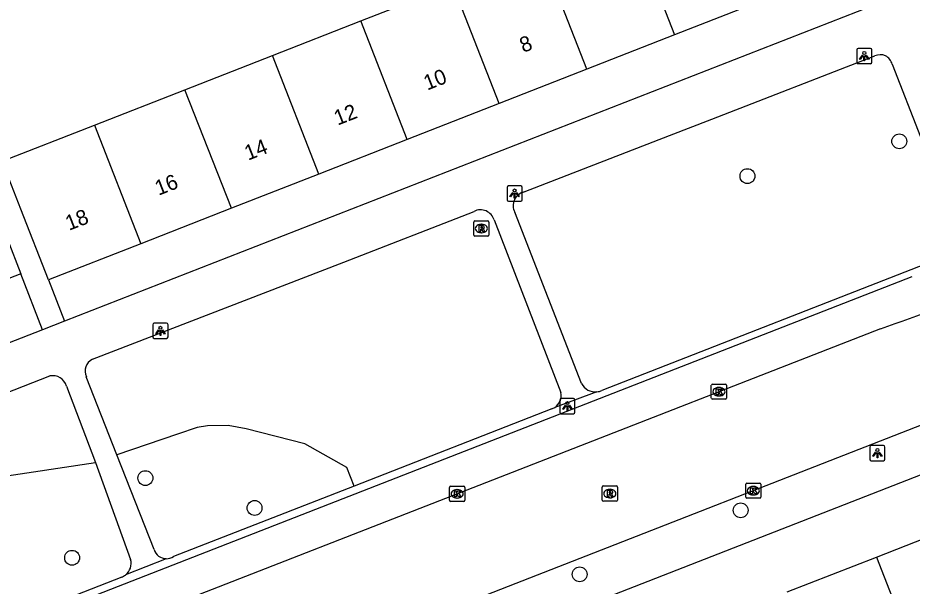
# Model space of a CAD drawing. Extents: x 159689 to 160786, y 387323 to 388339.
# Drawn here: x 160126.1 to 160185.1, y 387702.9 to 387740.3 of the extents above; entities that cross this region are included whole.
import ezdxf

# ---------------------------------------------------------------- set-up
doc = ezdxf.new("R2010")
doc.units = 0
for name, color, linetype in [('IMGEO_Boom', 7, 'Continuous'), ('IMGEO_Groenvoorziening', 7, 'Continuous'), ('IMGEO_Kolk', 7, 'Continuous'), ('IMGEO_Lichtpunt', 7, 'Continuous'), ('IMGEO_Pand', 7, 'Continuous'), ('IMGEO_Pand_nummerreeks', 7, 'Continuous'), ('IMGEO_Rijbaan_lokaal_open', 7, 'Continuous'), ('IMGEO_Rioolput', 7, 'Continuous'), ('IMGEO_Voetpad_open', 7, 'Continuous')]:
    doc.layers.add(name, color=color, linetype=linetype)

msp = doc.modelspace()

# ---------------------------------------------------------------- linework, layer by layer
at = {"layer": 'IMGEO_Boom'}
for centre in [(160184.219, 387732.211), (160174.216, 387729.919), (160134.54, 387710.022), (160141.733, 387708.056), (160173.765, 387707.9), (160129.711, 387704.77), (160163.156, 387703.68)]:
    msp.add_circle(centre, 0.489, dxfattribs=at)
at = {"layer": 'IMGEO_Groenvoorziening'}
for points in [[(160148.302, 387709.499), (160147.822, 387710.72), (160145.048, 387712.284), (160141.184, 387713.26), (160139.991, 387713.483), (160138.623, 387713.466), (160137.948, 387713.351), (160136.653, 387712.912), (160132.659, 387711.561)], [(160102.286, 387697.335), (160106.239, 387698.209), (160113.688, 387699.856), (160119.673, 387708.148), (160120.152, 387708.72), (160120.74, 387709.179), (160121.41, 387709.507), (160122.18, 387709.694), (160131.248, 387711.047)]]:
    msp.add_lwpolyline(points, dxfattribs=at)
at = {"layer": 'IMGEO_Kolk'}
for p, q in [((160171.834, 387715.286), (160171.834, 387716.138)), ((160171.909, 387716.212), (160172.761, 387716.212)), ((160172.835, 387716.138), (160172.835, 387715.286)), ((160172.322, 387715.992), (160172.347, 387715.992)), ((160172.761, 387715.212), (160171.909, 387715.212)), ((160172.345, 387715.432), (160172.32, 387715.432)), ((160174.103, 387708.763), (160174.103, 387709.615)), ((160174.178, 387709.689), (160175.03, 387709.689)), ((160175.104, 387709.615), (160175.104, 387708.763)), ((160154.584, 387708.559), (160154.584, 387709.411)), ((160154.659, 387709.485), (160155.511, 387709.485)), ((160155.072, 387709.265), (160155.097, 387709.265)), ((160155.585, 387709.411), (160155.585, 387708.559)), ((160174.591, 387709.469), (160174.616, 387709.469)), ((160155.511, 387708.485), (160154.659, 387708.485)), ((160155.095, 387708.705), (160155.07, 387708.705)), ((160175.03, 387708.689), (160174.178, 387708.689)), ((160174.614, 387708.909), (160174.589, 387708.909))]:
    msp.add_line(p, q, dxfattribs=at)
for points in [[(160171.834, 387715.286), (160171.834, 387716.138)], [(160171.909, 387716.212), (160172.761, 387716.212)], [(160172.835, 387716.138), (160172.835, 387715.286)], [(160172.155, 387715.912), (160172.278, 387715.912), (160172.278, 387715.761), (160172.408, 387715.912), (160172.572, 387715.912), (160172.426, 387715.761), (160172.579, 387715.512), (160172.427, 387715.512), (160172.342, 387715.676), (160172.278, 387715.609), (160172.278, 387715.512), (160172.155, 387715.512), (160172.155, 387715.912)], [(160172.761, 387715.212), (160171.909, 387715.212)], [(160174.103, 387708.763), (160174.103, 387709.615)], [(160174.178, 387709.689), (160175.03, 387709.689)], [(160175.104, 387709.615), (160175.104, 387708.763)], [(160154.584, 387708.559), (160154.584, 387709.411)], [(160154.659, 387709.485), (160155.511, 387709.485)], [(160154.905, 387709.185), (160155.028, 387709.185), (160155.028, 387709.034), (160155.158, 387709.185), (160155.322, 387709.185), (160155.176, 387709.034), (160155.329, 387708.785), (160155.177, 387708.785), (160155.092, 387708.949), (160155.028, 387708.882), (160155.028, 387708.785), (160154.905, 387708.785), (160154.905, 387709.185)], [(160155.585, 387709.411), (160155.585, 387708.559)], [(160174.424, 387709.389), (160174.547, 387709.389), (160174.547, 387709.238), (160174.677, 387709.389), (160174.841, 387709.389), (160174.695, 387709.238), (160174.848, 387708.989), (160174.696, 387708.989), (160174.611, 387709.153), (160174.547, 387709.086), (160174.547, 387708.989), (160174.424, 387708.989), (160174.424, 387709.389)], [(160155.511, 387708.485), (160154.659, 387708.485)], [(160175.03, 387708.689), (160174.178, 387708.689)]]:
    msp.add_lwpolyline(points, dxfattribs=at)
for centre, start, end in [((160171.911, 387716.136), 91.55205, 178.44795), ((160171.911, 387716.136), 91.55205, 178.44795), ((160172.759, 387716.136), 1.55205, 88.44795), ((160172.759, 387716.136), 1.55205, 88.44795), ((160171.911, 387715.288), 181.55205, 268.44795), ((160171.911, 387715.288), 181.55205, 268.44795), ((160172.759, 387715.288), 271.55205, 358.44795), ((160172.759, 387715.288), 271.55205, 358.44795), ((160174.18, 387709.613), 91.55205, 178.44795), ((160174.18, 387709.613), 91.55205, 178.44795), ((160175.028, 387709.613), 1.55205, 88.44795), ((160175.028, 387709.613), 1.55205, 88.44795), ((160154.661, 387709.409), 91.55205, 178.44795), ((160154.661, 387709.409), 91.55205, 178.44795), ((160155.509, 387709.409), 1.55205, 88.44795), ((160155.509, 387709.409), 1.55205, 88.44795), ((160154.661, 387708.561), 181.55205, 268.44795), ((160154.661, 387708.561), 181.55205, 268.44795), ((160155.509, 387708.561), 271.55205, 358.44795), ((160155.509, 387708.561), 271.55205, 358.44795), ((160174.18, 387708.765), 181.55205, 268.44795), ((160174.18, 387708.765), 181.55205, 268.44795), ((160175.028, 387708.765), 271.55205, 358.44795), ((160175.028, 387708.765), 271.55205, 358.44795)]:
    msp.add_arc(centre, 0.0765, start, end, dxfattribs=at)
for centre, major_axis, ratio, start_param, end_param in [((160172.321, 387715.712), (-0.387, 0.002), 0.722429, 4.712389, 7.853982), ((160172.346, 387715.712), (-0.39, 0.002), 0.717154, 1.570796, 4.712389), ((160155.071, 387708.985), (-0.387, 0.002), 0.722429, 4.712389, 7.853982), ((160155.096, 387708.985), (-0.39, 0.002), 0.717154, 1.570796, 4.712389), ((160174.59, 387709.189), (-0.387, 0.002), 0.722429, 4.712389, 7.853982), ((160174.615, 387709.189), (-0.39, 0.002), 0.717154, 1.570796, 4.712389)]:
    msp.add_ellipse(centre, major_axis=major_axis, ratio=ratio, start_param=start_param, end_param=end_param, dxfattribs=at)
at = {"layer": 'IMGEO_Lichtpunt'}
for p, q in [((160181.415, 387738.231), (160181.415, 387737.424)), ((160181.415, 387738.231), (160181.415, 387737.424)), ((160182.317, 387738.326), (160181.509, 387738.326)), ((160182.317, 387738.326), (160181.509, 387738.326)), ((160182.411, 387737.424), (160182.411, 387738.231)), ((160182.411, 387737.424), (160182.411, 387738.231)), ((160181.509, 387737.33), (160182.317, 387737.33)), ((160181.509, 387737.33), (160182.317, 387737.33)), ((160158.37, 387729.175), (160158.37, 387728.368)), ((160158.37, 387729.175), (160158.37, 387728.368)), ((160159.272, 387729.27), (160158.464, 387729.27)), ((160159.272, 387729.27), (160158.464, 387729.27)), ((160159.366, 387728.368), (160159.366, 387729.175)), ((160159.366, 387728.368), (160159.366, 387729.175)), ((160158.464, 387728.274), (160159.272, 387728.274)), ((160158.464, 387728.274), (160159.272, 387728.274)), ((160135.935, 387720.226), (160135.127, 387720.226)), ((160135.935, 387720.226), (160135.127, 387720.226)), ((160135.033, 387720.131), (160135.033, 387719.324)), ((160135.033, 387720.131), (160135.033, 387719.324)), ((160136.029, 387719.324), (160136.029, 387720.131)), ((160136.029, 387719.324), (160136.029, 387720.131)), ((160135.127, 387719.23), (160135.935, 387719.23)), ((160135.127, 387719.23), (160135.935, 387719.23)), ((160161.853, 387715.167), (160161.853, 387714.36)), ((160161.853, 387715.167), (160161.853, 387714.36)), ((160162.755, 387715.262), (160161.947, 387715.262)), ((160162.755, 387715.262), (160161.947, 387715.262)), ((160162.849, 387714.36), (160162.849, 387715.167)), ((160162.849, 387714.36), (160162.849, 387715.167)), ((160161.947, 387714.266), (160162.755, 387714.266)), ((160161.947, 387714.266), (160162.755, 387714.266)), ((160182.28, 387712.071), (160182.28, 387711.264)), ((160182.28, 387712.071), (160182.28, 387711.264)), ((160183.182, 387712.166), (160182.374, 387712.166)), ((160183.182, 387712.166), (160182.374, 387712.166)), ((160183.276, 387711.264), (160183.276, 387712.071)), ((160183.276, 387711.264), (160183.276, 387712.071)), ((160182.374, 387711.17), (160183.182, 387711.17)), ((160182.374, 387711.17), (160183.182, 387711.17))]:
    msp.add_line(p, q, dxfattribs=at)
for points in [[(160181.789, 387737.895), (160181.828, 387737.867), (160181.64, 387737.605), (160181.602, 387737.632), (160181.789, 387737.895)], [(160182.001, 387737.867), (160182.039, 387737.894), (160182.226, 387737.632), (160182.187, 387737.604), (160182.001, 387737.867)], [(160181.891, 387737.847), (160181.938, 387737.847), (160181.938, 387737.525), (160181.891, 387737.525), (160181.891, 387737.847)], [(160158.744, 387728.839), (160158.783, 387728.811), (160158.595, 387728.549), (160158.557, 387728.576), (160158.744, 387728.839)], [(160158.846, 387728.791), (160158.893, 387728.791), (160158.893, 387728.469), (160158.846, 387728.469), (160158.846, 387728.791)], [(160158.956, 387728.811), (160158.994, 387728.838), (160159.181, 387728.576), (160159.142, 387728.548), (160158.956, 387728.811)], [(160135.407, 387719.795), (160135.446, 387719.767), (160135.258, 387719.505), (160135.22, 387719.532), (160135.407, 387719.795)], [(160135.509, 387719.747), (160135.556, 387719.747), (160135.556, 387719.425), (160135.509, 387719.425), (160135.509, 387719.747)], [(160135.619, 387719.767), (160135.657, 387719.794), (160135.844, 387719.532), (160135.805, 387719.504), (160135.619, 387719.767)], [(160162.227, 387714.831), (160162.266, 387714.803), (160162.078, 387714.541), (160162.04, 387714.568), (160162.227, 387714.831)], [(160162.329, 387714.783), (160162.376, 387714.783), (160162.376, 387714.461), (160162.329, 387714.461), (160162.329, 387714.783)], [(160162.439, 387714.803), (160162.477, 387714.83), (160162.664, 387714.568), (160162.625, 387714.54), (160162.439, 387714.803)], [(160182.654, 387711.735), (160182.693, 387711.707), (160182.505, 387711.445), (160182.467, 387711.472), (160182.654, 387711.735)], [(160182.756, 387711.687), (160182.803, 387711.687), (160182.803, 387711.365), (160182.756, 387711.365), (160182.756, 387711.687)], [(160182.866, 387711.707), (160182.904, 387711.734), (160183.091, 387711.472), (160183.052, 387711.444), (160182.866, 387711.707)]]:
    msp.add_lwpolyline(points, dxfattribs=at)
for centre in [(160181.914, 387738.029), (160158.869, 387728.973), (160135.532, 387719.929), (160162.352, 387714.965), (160182.779, 387711.869)]:
    msp.add_circle(centre, 0.0994, dxfattribs=at)
for centre, start, end in [((160181.509, 387738.231), 90, 180), ((160181.509, 387738.231), 90, 180), ((160182.317, 387738.231), 0, 90), ((160182.317, 387738.231), 0, 90), ((160181.509, 387737.424), 180, 270), ((160181.509, 387737.424), 180, 270), ((160182.317, 387737.424), 270, 0), ((160182.317, 387737.424), 270, 360), ((160158.464, 387729.175), 90, 180), ((160158.464, 387729.175), 90, 180), ((160159.272, 387729.175), 0, 90), ((160159.272, 387729.175), 0, 90), ((160158.464, 387728.368), 180, 270), ((160158.464, 387728.368), 180, 270), ((160159.272, 387728.368), 270, 0), ((160159.272, 387728.368), 270, 360), ((160135.127, 387720.131), 90, 180), ((160135.127, 387720.131), 90, 180), ((160135.935, 387720.131), 0, 90), ((160135.935, 387720.131), 0, 90), ((160135.127, 387719.324), 180, 270), ((160135.127, 387719.324), 180, 270), ((160135.935, 387719.324), 270, 0), ((160135.935, 387719.324), 270, 360), ((160161.947, 387715.167), 90, 180), ((160161.947, 387715.167), 90, 180), ((160162.755, 387715.167), 0, 90), ((160162.755, 387715.167), 0, 90), ((160161.947, 387714.36), 180, 270), ((160161.947, 387714.36), 180, 270), ((160162.755, 387714.36), 270, 0), ((160162.755, 387714.36), 270, 360), ((160182.374, 387712.071), 90, 180), ((160182.374, 387712.071), 90, 180), ((160183.182, 387712.071), 0, 90), ((160183.182, 387712.071), 0, 90), ((160182.374, 387711.264), 180, 270), ((160182.374, 387711.264), 180, 270), ((160183.182, 387711.264), 270, 0), ((160183.182, 387711.264), 270, 360)]:
    msp.add_arc(centre, 0.0946, start, end, dxfattribs=at)
at = {"layer": 'IMGEO_Pand'}
for points in [[(160166.354, 387747.05), (160169.414, 387739.232)], [(160163.629, 387736.967), (160160.569, 387744.785)], [(160148.737, 387740.152), (160154.794, 387742.524)], [(160157.854, 387734.706), (160154.794, 387742.524)], [(160175.382, 387741.569), (160169.414, 387739.232)], [(160142.914, 387737.872), (160148.737, 387740.152)], [(160151.797, 387732.335), (160148.737, 387740.152)], [(160169.414, 387739.232), (160163.629, 387736.967)], [(160137.147, 387735.615), (160142.914, 387737.872)], [(160145.974, 387730.055), (160142.914, 387737.872)], [(160163.629, 387736.967), (160157.854, 387734.706)], [(160131.174, 387733.276), (160137.147, 387735.615)], [(160140.208, 387727.798), (160137.147, 387735.615)], [(160157.854, 387734.706), (160151.797, 387732.335)], [(160125.095, 387730.896), (160131.174, 387733.276)], [(160131.174, 387733.276), (160134.234, 387725.459)], [(160151.797, 387732.335), (160145.974, 387730.055)], [(160123.244, 387731.379), (160124.508, 387728.141), (160126.325, 387723.483)], [(160128.155, 387723.079), (160126.332, 387727.735), (160125.095, 387730.896)], [(160145.974, 387730.055), (160140.208, 387727.798)], [(160140.208, 387727.798), (160134.234, 387725.459)], [(160134.234, 387725.459), (160128.155, 387723.079)], [(160126.325, 387723.483), (160120.563, 387721.235)], [(160182.71, 387704.816), (160188.578, 387707.108)], [(160176.842, 387702.524), (160182.71, 387704.816)], [(160182.71, 387704.816), (160185.791, 387696.929)]]:
    msp.add_lwpolyline(points, dxfattribs=at)
at = {"layer": 'IMGEO_Rijbaan_lokaal_open'}
for points in [[(160182.985, 387719.864), (160133.651, 387700.624), (160089.312, 387683.27), (160055.434, 387670.196)], [(160190, 387715.208), (160155.133, 387701.581), (160119.003, 387687.495), (160085.401, 387674.408), (160057.185, 387663.329)]]:
    msp.add_lwpolyline(points, dxfattribs=at)
msp.add_arc((160142.899, 387835.721), 122.596, 289.08558, 292.87789, dxfattribs=at)
at = {"layer": 'IMGEO_Rioolput'}
for p, q in [((160156.179, 387726.04), (160156.179, 387726.892)), ((160156.254, 387726.966), (160157.106, 387726.966)), ((160156.667, 387726.746), (160156.692, 387726.746)), ((160157.18, 387726.892), (160157.18, 387726.04)), ((160156.69, 387726.186), (160156.665, 387726.186)), ((160157.106, 387725.966), (160156.254, 387725.966)), ((160164.643, 387708.576), (160164.643, 387709.428)), ((160164.718, 387709.502), (160165.57, 387709.502)), ((160165.131, 387709.282), (160165.156, 387709.282)), ((160165.644, 387709.428), (160165.644, 387708.576)), ((160165.57, 387708.502), (160164.718, 387708.502)), ((160165.154, 387708.722), (160165.129, 387708.722))]:
    msp.add_line(p, q, dxfattribs=at)
for points in [[(160156.179, 387726.04), (160156.179, 387726.892)], [(160156.254, 387726.966), (160157.106, 387726.966)], [(160157.18, 387726.892), (160157.18, 387726.04)], [(160156.768, 387726.664), (160156.516, 387726.666), (160156.516, 387726.266)], [(160156.516, 387726.266), (160156.64, 387726.266), (160156.64, 387726.428), (160156.651, 387726.428)], [(160156.694, 387726.585), (160156.64, 387726.585), (160156.64, 387726.504)], [(160156.64, 387726.504), (160156.692, 387726.504)], [(160156.698, 387726.399), (160156.769, 387726.266), (160156.909, 387726.266), (160156.844, 387726.392)], [(160157.106, 387725.966), (160156.254, 387725.966)], [(160164.643, 387708.576), (160164.643, 387709.428)], [(160164.718, 387709.502), (160165.57, 387709.502)], [(160165.232, 387709.2), (160164.98, 387709.202), (160164.98, 387708.802)], [(160165.158, 387709.121), (160165.104, 387709.121), (160165.104, 387709.04)], [(160165.104, 387709.04), (160165.156, 387709.04)], [(160165.644, 387709.428), (160165.644, 387708.576)], [(160165.57, 387708.502), (160164.718, 387708.502)], [(160164.98, 387708.802), (160165.104, 387708.802), (160165.104, 387708.964), (160165.115, 387708.964)], [(160165.162, 387708.935), (160165.233, 387708.802), (160165.373, 387708.802), (160165.308, 387708.928)]]:
    msp.add_lwpolyline(points, dxfattribs=at)
for centre, radius, start, end in [((160156.256, 387726.89), 0.0765, 91.55205, 178.44795), ((160156.256, 387726.89), 0.0765, 91.55205, 178.44795), ((160157.104, 387726.89), 0.0765, 1.55205, 88.44795), ((160157.104, 387726.89), 0.0765, 1.55205, 88.44795), ((160156.65, 387726.375), 0.0533, 26.02933, 88.69889), ((160156.676, 387726.693), 0.19, 274.7715, 282.96867), ((160156.7, 387726.489), 0.0964, 77.00612, 93.18647), ((160156.714, 387726.546), 0.0378, 276.66336, 79.67722), ((160156.767, 387726.554), 0.109, 350.36119, 89.41601), ((160156.765, 387726.554), 0.112, 277.58423, 350.98172), ((160156.749, 387726.339), 0.108, 29.51342, 73.79051), ((160156.256, 387726.042), 0.0765, 181.55205, 268.44795), ((160156.256, 387726.042), 0.0765, 181.55205, 268.44795), ((160157.104, 387726.042), 0.0765, 271.55205, 358.44795), ((160157.104, 387726.042), 0.0765, 271.55205, 358.44795), ((160164.72, 387709.426), 0.0765, 91.55205, 178.44795), ((160164.72, 387709.426), 0.0765, 91.55205, 178.44795), ((160165.14, 387709.229), 0.19, 274.7715, 282.96867), ((160165.164, 387709.025), 0.0964, 77.00612, 93.18647), ((160165.178, 387709.082), 0.0378, 276.66336, 79.67722), ((160165.231, 387709.09), 0.109, 350.36119, 89.41601), ((160165.229, 387709.09), 0.112, 277.58423, 350.98172), ((160165.568, 387709.426), 0.0765, 1.55205, 88.44795), ((160165.568, 387709.426), 0.0765, 1.55205, 88.44795), ((160164.72, 387708.578), 0.0765, 181.55205, 268.44795), ((160164.72, 387708.578), 0.0765, 181.55205, 268.44795), ((160165.114, 387708.911), 0.0533, 26.02933, 88.69889), ((160165.213, 387708.875), 0.108, 29.51342, 73.79051), ((160165.568, 387708.578), 0.0765, 271.55205, 358.44795), ((160165.568, 387708.578), 0.0765, 271.55205, 358.44795)]:
    msp.add_arc(centre, radius, start, end, dxfattribs=at)
for centre, major_axis, ratio, start_param, end_param in [((160156.666, 387726.466), (-0.387, 0.002), 0.722429, 4.712389, 7.853982), ((160156.691, 387726.466), (-0.39, 0.002), 0.717154, 1.570796, 4.712389), ((160165.13, 387709.002), (-0.387, 0.002), 0.722429, 4.712389, 7.853982), ((160165.155, 387709.002), (-0.39, 0.002), 0.717154, 1.570796, 4.712389)]:
    msp.add_ellipse(centre, major_axis=major_axis, ratio=ratio, start_param=start_param, end_param=end_param, dxfattribs=at)
at = {"layer": 'IMGEO_Voetpad_open'}
for points in [[(160182.349, 387741.102), (160129.215, 387720.362)], [(160159.506, 387728.878), (160169.084, 387732.594), (160171.857, 387733.67), (160182.613, 387737.838)], [(160183.749, 387737.288), (160185.621, 387732.5), (160188.102, 387726.158)], [(160131.046, 387717.852), (160147.626, 387724.241), (160156.198, 387727.597)], [(160163.289, 387716.263), (160158.875, 387727.534)], [(160157.521, 387727.036), (160161.925, 387715.665)], [(160187.794, 387724.84), (160164.624, 387715.802)], [(160057.664, 387673.563), (160058.019, 387673.764), (160088.425, 387685.547), (160132.762, 387702.9), (160185.066, 387723.299)], [(160127.764, 387719.796), (160126.325, 387723.483)], [(160128.155, 387723.079), (160129.215, 387720.362)], [(160129.215, 387720.362), (160127.764, 387719.796)], [(160127.764, 387719.796), (160068.881, 387696.811)], [(160100.09, 387705.736), (160116.68, 387712.231), (160128.251, 387716.753)], [(160132.659, 387711.561), (160130.646, 387716.699)], [(160129.329, 387716.088), (160131.248, 387711.047)], [(160164.29, 387715.705), (160161.51, 387714.671)], [(160161.326, 387714.581), (160148.302, 387709.499)], [(160140.108, 387692.465), (160193.051, 387713.133), (160193.266, 387713.204)], [(160135.109, 387705.309), (160132.659, 387711.561)], [(160131.248, 387711.047), (160133.564, 387704.662)], [(160148.302, 387709.499), (160136.384, 387704.848)], [(160135.909, 387704.713), (160133.223, 387703.637)], [(160132.975, 387703.497), (160105, 387692.567)]]:
    msp.add_lwpolyline(points, dxfattribs=at)
for centre, radius, start, end in [((160182.968, 387737.122), 0.799, 11.98233, 116.34932), ((160159.709, 387727.963), 0.937, 102.48174, 207.21871), ((160156.62, 387726.751), 0.946, 17.56683, 116.47575), ((160131.443, 387717.068), 0.878, 116.87137, 204.86315), ((160128.435, 387715.845), 0.926, 15.1974, 101.46313), ((160164.185, 387716.693), 0.994, 205.64945, 276.07624), ((160161.01, 387715.463), 0.937, 302.24322, 12.43522), ((160164.184, 387716.694), 0.995, 276.12556, 296.26306), ((160161.023, 387715.434), 0.906, 289.57114, 302.55819), ((160135.924, 387705.569), 0.856, 197.65766, 268.97012), ((160132.624, 387704.405), 0.974, 307.92, 15.27719), ((160135.919, 387705.583), 0.87, 269.37331, 302.35811), ((160132.617, 387704.42), 0.99, 291.17459, 307.71626)]:
    msp.add_arc(centre, radius, start, end, dxfattribs=at)

# ---------------------------------------------------------------- texts
at = {"layer": 'IMGEO_Pand_nummerreeks'}
for s, p in [('8', (160159.441, 387738.034)), ('10', (160153.111, 387735.555)), ('12', (160147.204, 387733.243)), ('14', (160141.305, 387730.934)), ('16', (160135.404, 387728.623)), ('18', (160129.505, 387726.314))]:
    msp.add_text(s, height=1, rotation=21.38059, dxfattribs=at).set_placement(p)

doc.saveas('drawing.dxf')
